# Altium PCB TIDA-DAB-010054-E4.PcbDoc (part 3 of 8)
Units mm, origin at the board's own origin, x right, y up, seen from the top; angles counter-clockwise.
Board outline 300 x 180 mm, 4 copper layers (Top Layer, Inner Layer1, Inner Layer2, Bottom Layer), stack 1.605 mm thick; 873 components, 388 nets, 2405 pads, 1542 vias.
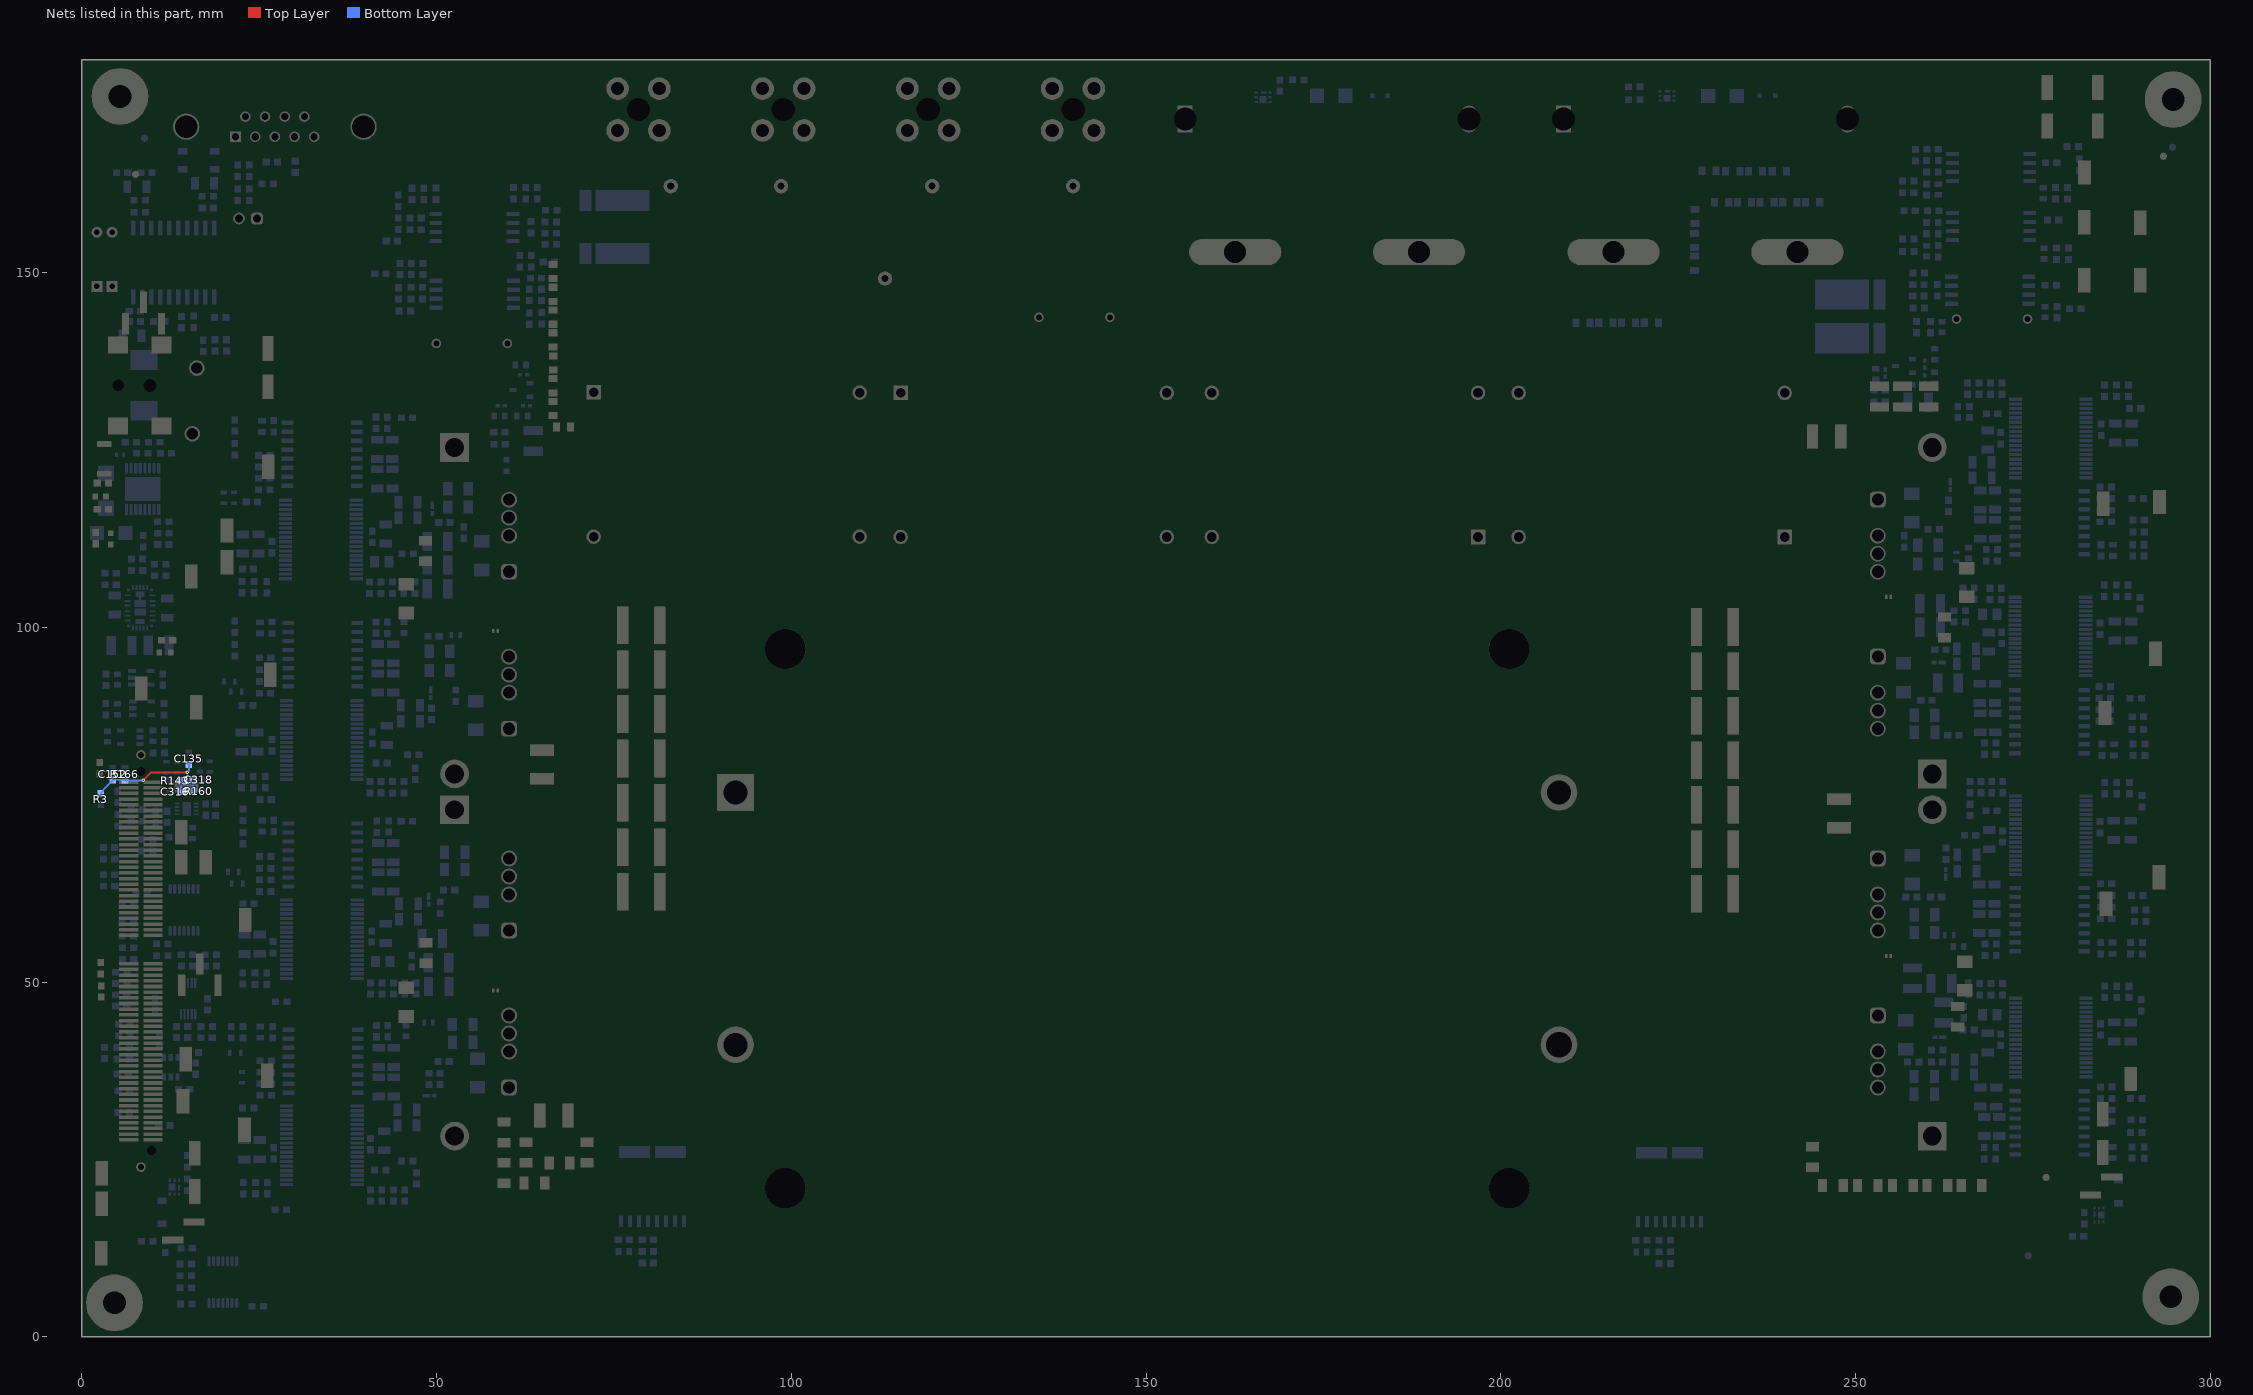
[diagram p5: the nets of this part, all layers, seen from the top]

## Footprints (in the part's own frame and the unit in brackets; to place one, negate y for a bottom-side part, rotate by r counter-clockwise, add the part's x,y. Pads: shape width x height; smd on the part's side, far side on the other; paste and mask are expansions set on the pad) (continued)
LTST-C193_Red [mm] "SMD, 2-Leads, Body1.6x0.8mm"
  rect 0.8x0.8 smd: 1(-0.75,0) 2(0.75,0)
  silkscreen extent -1.2,-0.9 1.85,0.9, body extent -0.85,-0.45 0.85,0.45, height 0.45
Mill-Max_999-11-113-10-000000 [mil] "Shorting Jumper, 7.62mm, 2 Position, Gold, TH"
  rect 60x60 hole 30: 1(-150,0)
  round 60 hole 30: 2(150,0)
  silkscreen extent -102,-12 98,12, body extent -161,-11 161,11, height 105
Net-Tie7milsWide_20milsLong [mil] "7 mils wide by 20 mils long"
  rect 10x7 smd paste-5 mask-5: 1(-5,0) 2(5,0)
"NY PMS 440 0025 PH" [mm] "4-40 nylon screw and mounting hole"
  round 8 hole 3.2: 1(0,0)
  body extent -3.3,-3.3 3.3,3.3, height 2.69
Pb-Free_Overlay_Medium [mm]
  silkscreen extent -2.41,-2.41 2.41,2.41
PW0014A_N [mm] "TSOP, 14-Leads, Body 5x4.4mm, Pitch 0.65mm, IPC Medium Density"
  oval 1.4x0.45 smd: 1(-2.95,1.95) 2(-2.95,1.3) 3(-2.95,0.65) 4(-2.95,0) 5(-2.95,-0.65) 6(-2.95,-1.3) 7(-2.95,-1.95) 8(2.95,-1.95) 9(2.95,-1.3) 10(2.95,-0.65) 11(2.95,0) 12(2.95,0.65) 13(2.95,1.3) 14(2.95,1.95)
  silkscreen extent -3.4,-2.55 1.85,2.55, body extent -3.21,-2.5 3.21,2.5, height 1
PWP0016H-MFG [mm]
  rrect22% 1.5x0.45 smd paste+0 mask+0: 1(-2.9,2.275) 2(-2.9,1.625) 3(-2.9,0.975) 4(-2.9,0.325) 5(-2.9,-0.325) 6(-2.9,-0.975) 7(-2.9,-1.625) 8(-2.9,-2.275) 9(2.9,-2.275) 10(2.9,-1.625) 11(2.9,-0.975) 12(2.9,-0.325) 13(2.9,0.325) 14(2.9,0.975) 15(2.9,1.625) 16(2.9,2.275)
  rrect3% 3.4x5 smd paste-1000 mask-1000: 17(0,0)
  silkscreen extent -4.32,-2.95 2.25,2.95, body extent -3.2,-2.5 3.2,2.5, height 1.2
RDH0030A-MFG [mm]
  round 0.419 smd paste+0 mask+0: 1(-1.633,2.508) 21(1.633,2.508)
  rrect40% 0.85x0.25 smd paste+0 mask+0: 2(-1.775,1.775) 3(-1.775,0.975) 4(-1.775,0.325) 5(-1.775,-0.475) 6(-1.775,-1.125) 7(-1.775,-1.775) 15(1.775,-1.775) 16(1.775,-1.125) 17(1.775,-0.475) 18(1.775,0.325) 19(1.775,0.975) 20(1.775,1.775)
  round 0.407 smd paste+0 mask+0: 8(-1.633,-2.53) 14(1.633,-2.53)
  rrect40% 0.25x0.7 smd paste+0 mask+0: 9(-1,-2.85) 10(-0.5,-2.85) 11(0,-2.85) 12(0.5,-2.85) 13(1,-2.85) 22(1,2.85) 23(0.5,2.85) 24(0,2.85) 25(-0.5,2.85) 26(-1,2.85)
  rrect14% 1.25x0.74 smd paste-1000 mask-1000: 27(0,1.925) 30(0,-1.925)
  rrect10% 1.6x1 smd paste-1000 mask-1000: 28(0,0.6) 29(0,-0.6)
  Top Layer region: 2.2,2.35 2.196,2.331 2.185,2.315 2.169,2.304 2.15,2.3 2.15,2.3 1.875,2.3 1.871,2.281 1.86,2.265 1.844,2.254 1.825,2.25 1.825,2.25 1.425,2.25 1.406,2.254 1.39,2.265 1.379,2.281 1.375,2.3 1.375,2.3 1.375,3.15 1.379,3.169 1.39,3.185 1.406,3.196 1.425,3.2 1.425,3.2 1.575,3.2 1.6,3.193 1.618,3.175 1.625,3.15 1.625,3.15 1.625,2.925 1.629,2.906 1.64,2.89 1.656,2.879 1.675,2.875 1.675,2.875 1.8,2.875 1.825,2.868 1.843,2.85 1.85,2.825 1.85,2.825 1.85,2.6 1.854,2.581 1.865,2.565 1.881,2.554 1.9,2.55 1.9,2.55 2.15,2.55 2.175,2.543 2.193,2.525 2.2,2.5 2.2,2.5
  Top Layer region: 2.2,-2.35 2.196,-2.331 2.185,-2.315 2.169,-2.304 2.15,-2.3 2.15,-2.3 1.875,-2.3 1.871,-2.281 1.86,-2.265 1.844,-2.254 1.825,-2.25 1.825,-2.25 1.425,-2.25 1.406,-2.254 1.39,-2.265 1.379,-2.281 1.375,-2.3 1.375,-2.3 1.375,-3.15 1.379,-3.169 1.39,-3.185 1.406,-3.196 1.425,-3.2 1.425,-3.2 1.575,-3.2 1.6,-3.193 1.618,-3.175 1.625,-3.15 1.625,-3.15 1.625,-2.925 1.629,-2.906 1.64,-2.89 1.656,-2.879 1.675,-2.875 1.675,-2.875 1.8,-2.875 1.825,-2.868 1.843,-2.85 1.85,-2.825 1.85,-2.825 1.85,-2.6 1.854,-2.581 1.865,-2.565 1.881,-2.554 1.9,-2.55 1.9,-2.55 2.15,-2.55 2.175,-2.543 2.193,-2.525 2.2,-2.5 2.2,-2.5
  Top Layer region: -2.2,-2.35 -2.196,-2.331 -2.185,-2.315 -2.169,-2.304 -2.15,-2.3 -2.15,-2.3 -1.875,-2.3 -1.871,-2.281 -1.86,-2.265 -1.844,-2.254 -1.825,-2.25 -1.825,-2.25 -1.425,-2.25 -1.406,-2.254 -1.39,-2.265 -1.379,-2.281 -1.375,-2.3 -1.375,-2.3 -1.375,-3.15 -1.379,-3.169 -1.39,-3.185 -1.406,-3.196 -1.425,-3.2 -1.425,-3.2 -1.575,-3.2 -1.6,-3.193 -1.618,-3.175 -1.625,-3.15 -1.625,-3.15 -1.625,-2.925 -1.629,-2.906 -1.64,-2.89 -1.656,-2.879 -1.675,-2.875 -1.675,-2.875 -1.8,-2.875 -1.825,-2.868 -1.843,-2.85 -1.85,-2.825 -1.85,-2.825 -1.85,-2.6 -1.854,-2.581 -1.865,-2.565 -1.881,-2.554 -1.9,-2.55 -1.9,-2.55 -2.15,-2.55 -2.175,-2.543 -2.193,-2.525 -2.2,-2.5 -2.2,-2.5
  Top Layer region: -2.2,2.35 -2.196,2.331 -2.185,2.315 -2.169,2.304 -2.15,2.3 -2.15,2.3 -1.875,2.3 -1.871,2.281 -1.86,2.265 -1.844,2.254 -1.825,2.25 -1.825,2.25 -1.425,2.25 -1.406,2.254 -1.39,2.265 -1.379,2.281 -1.375,2.3 -1.375,2.3 -1.375,3.15 -1.379,3.169 -1.39,3.185 -1.406,3.196 -1.425,3.2 -1.425,3.2 -1.575,3.2 -1.6,3.193 -1.618,3.175 -1.625,3.15 -1.625,3.15 -1.625,2.925 -1.629,2.906 -1.64,2.89 -1.656,2.879 -1.675,2.875 -1.675,2.875 -1.8,2.875 -1.825,2.868 -1.843,2.85 -1.85,2.825 -1.85,2.825 -1.85,2.6 -1.854,2.581 -1.865,2.565 -1.881,2.554 -1.9,2.55 -1.9,2.55 -2.15,2.55 -2.175,2.543 -2.193,2.525 -2.2,2.5 -2.2,2.5
  silkscreen extent -2.42,-3.65 2.05,3.65, body extent -2,-3 2,3, height 1.9
SMA [mm] "Molded Diode, 2-Leads, Body 4.3x2.6mm, IPC Medium Density, based on OnSemi component dimensions and land pattern"
  rect 2x2 smd: 1(-2,0) 2(2,0)
  silkscreen extent -3.66,-1.57 2.79,1.57, body extent -2.6,-1.3 2.6,1.3, height 2.42
SMC_Bi [mil] "SMC, no polarity mark"
  rect 110x150 smd: 1(-140.49,0) 2(140.49,0)
  body extent -156,-116 156,116, height 92
SOD-123 [mm] "On Semi recommended land pattern"
  rect 0.915x1.22 smd: 1(-1.637,0) 2(1.637,0)
  silkscreen extent -2.74,-1.17 2.03,1.17, body extent -1.93,-0.9 1.93,0.9, height 1.35
SOD-323 [mm] "NXP recommended land pattern"
  rect 0.6x0.6 smd paste-0.05: 1(-1.1,0) 2(1.1,0)
  silkscreen extent -2.06,-0.86 1.53,0.86, body extent -1.3,-0.67 1.3,0.68, height 1.1
SW_SKRKAE [mm] "SMD, 2-Leads, Body 3.9x2.9mm"
  rrect12% 0.8x2 smd: 1(-2.1,0) 2(2.1,0)
  body extent -2.4,-1.45 2.4,1.45, height 2
Testpoint_Keystone_Miniature [mil] "Miniature SMT test point"
  rect 135x70 smd: 1(0,0)
  silkscreen extent -78,-46 78,45, body extent -52,-20 52,20, height 61
TI_Stacked_Overlay_Small [mm]
  silkscreen extent -10.63,-2.49 10.63,2.49
TNPW0603 [mm] "Vishay"
  rect 0.5x0.9 smd: 1(-0.75,0) 2(0.75,0)
  silkscreen extent -0.2,-0.6 0.2,0.6, body extent -0.85,-0.47 0.85,0.47, height 0.55
TO-247-4 [mm] "FM, 4-Leads, Body 15.94x5.02mm, Pitch 2.54mm"
  rrect50% 2.24x2.24 hole 1.7: 1(-5.08,0)
  round 2.24 hole 1.7: 2(0,0) 3(2.54,0) 4(5.08,0)
  silkscreen extent -8.07,-2.49 8.07,2.72, body extent -8.07,-2.49 8.07,2.72, height 27.97
UWT_630x770 [mm] "SMD, 2-Leads, Dia 6.3mm"
  rrect6% 3.5x1.6 smd: 1(-2.7,0) 2(2.7,0)
  body extent -3.5,-3.3 3.5,3.3, height 8
WEEE_Minimum [mm] "WEEElie bin"
  silkscreen extent -2.42,-4.38 2.52,2.65
WL-SMCW_GREEN [mm] "WURTH"
  rect 0.8x0.8 smd: 1(-0.8,0) 2(0.8,0)
  silkscreen extent -1.9,-0.8 1.2,0.8, body extent -0.85,-0.45 0.85,0.45, height 0.8
WSL3637_0_002 [mil] "Vishay WSL3637 recommended land pattern for 0.002 to 0.01 Ohm"
  rect 116x300 smd: 1(-147,-45) 2(147,-45)
  rect 116x66 smd: 3(-147,162) 4(147,162)
  silkscreen extent -220,-210 220,210, body extent -185,-190 185,190, height 35
Wurth_61000218321 [mm] "Header, 2.54mm, 2x1, SMT"
  rect 1x3 smd: 1(-1.27,1.5) 2(1.27,-1.5)
  silkscreen extent -2.86,-1.27 2.54,1.27, body extent -2.54,-2.5 2.54,2.5, height 6.3
Wurth_61000318221 [mm] "Header, 2.54mm, 3x1, SMT"
  rrect10% 3x1 smd: 1(-1.4,2.54) 2(1.6,0) 3(-1.4,-2.54)
  body extent -2.5,-3.81 2.5,3.81, height 9.33
WURTH_61300211121 [mm] "Header, 2.54mm, 2x1, TH"
  rrect50% 1.65x1.65 hole 1.15: 1(-1.27,0)
  round 1.65 hole 1.15: 2(1.27,0)
  body extent -2.54,-1.27 2.54,1.27, height 8.54
Wurth_618009231121 [mm] "Receptacle, D-Sub, 9 Position, R/A, TH"
  rect 1.5x1.5 hole 1: 1(-10.92,5.54)
  round 1.5 hole 1: 2(-10.92,2.77) 3(-10.92,0) 4(-10.92,-2.77) 5(-10.92,-5.54) 6(-8.08,4.155) 7(-8.08,1.385) 8(-8.08,-1.385) 9(-8.08,-4.155)
  round 3.7 hole 3.2: 10(-9.5,12.5) 11(-9.5,-12.5)
  silkscreen extent -12.78,-15.4 -0.53,15.4, body extent -12.5,-15.4 6,15.4, height 12.5
Wurth_WP-THRBU [mm] "Power Element Bush, M3, TH"
  round 3.2 hole 1.85: 1(-2.935,-2.935) 1(-2.935,2.935) 1(2.935,-2.935) 1(2.935,2.935)
  round 3.1 on Top Paste: ""(-2.935,-2.935) ""(-2.935,2.935) ""(2.935,-2.935) ""(2.935,2.935)
  round 3 hole 3.3 unplated mask+0.102: ""(0,0)
  silkscreen extent -3.5,-3.5 3.5,3.5, body extent -3.5,-3.5 3.5,3.5, height 3

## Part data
C1 C4 C6 C12 C313 C319 C320 C321 C322: library part CMP-0006848-4, "CAP, CERM, 0.01 uF, 100 V, +/- 5%, X7R, 0603", Cap_Case=0603, Manufacturer=Kemet, Supplier Part Number 1=399-3190-1-ND, TempCo=X7R, Tolerance_%=5%, Value1=Unknown, Value2=100V, ValueDisplayed=0.01uF
C2 C8 C14: library part CMP-0080740-1, "CAP, CERM, 10 µF, 25 V,+/- 10%, X7R, 1206", Cap_Case=1206, Manufacturer=TDK, Supplier Part Number 1=445-7705-1-ND, TempCo=X7R, Tolerance_%=10%, Value2=25V, ValueDisplayed=10µF
C3 C7 C13: library part CMP-0085302-1, "CAP, CERM, 1 µF, 16 V,+/- 10%, X7R, AEC-Q200 Grade 1, 0603", Cap_Case=0603, Manufacturer="Samsung Electro-Mechanics", TempCo=X7R, Tolerance_%=10%, Value2=16V, ValueDisplayed=1µF
C5 C154 C197: library part CMP-0006837-4, "CAP, CERM, 0.1 uF, 50 V, +/- 10%, X7R, 0603", Cap_Case=0603, Manufacturer="Wurth Elektronik", TempCo=X7R, Tolerance_%=10%, Value1=Unknown, Value2=50V, ValueDisplayed=0.1uF
C9 C11: library part CMP-0007220-4, "CAP, CERM, 47 pF, 50 V, +/- 5%, C0G/NP0, 0603", Cap_Case=0603, Manufacturer=MuRata, Supplier Part Number 1=490-1419-1-ND, TempCo=C0G/NP0, Tolerance_%=5%, Value1=Unknown, Value2=50V, ValueDisplayed=47pF
C10: library part CMP-0006987-4, "CAP, CERM, 4700 pF, 50 V, +/- 10%, X7R, 0603", Cap_Case=0603, Manufacturer=Kemet, Supplier Part Number 1=399-5337-1-ND, TempCo=X7R, Tolerance_%=10%, Value1=Unknown, Value2=50V, ValueDisplayed=4700pF
C15 C16 C19 C20 C25 C26 C28 C30: library part CMP-0009324-2, "CAP, CERM, 0.1 uF, 1000 V, +/- 10%, X7R, 1812", Cap_Case=1812, Manufacturer=Kemet, Supplier Part Number 1=399-6493-1-ND, TempCo=X7R, Tolerance_%=10%, Value1=Unknown, Value2=1000V, ValueDisplayed=0.1uF
C21 C22: library part CMP-0120640-1, "30 µF Film Capacitor 800V Polypropylene (PP), Metallized Radial - 4 Leads", Digikey Part Number=495-B32716H8306K000-ND, Manufacturer=TDK, Mouser Part Number=871-B32716H8306K000, Operating Temperature Range="-55°C to +105°C", Tolerance_%=10%, ValueDisplayed=30uF
C23 C24: library part CMP-0120639-1, "Power Film Capacitor, 15 uF, 1.1 kVDC, ± 10%, Metallized PP, Radial Box - 4 Pin, Through Hole", Digikey Part Number=495-B32716H1156K000-ND, Manufacturer=TDK, Mouser Part Number=871-B32716H1156K000, Operating Temperature Range="-55°C to +105°C", Tolerance_%=10%, ValueDisplayed=15uF
C31 C33 C35 C37 C39 C41 C43 C45 C47 C49 C51 C53 C55 C57: library part CMP-0086177-1, "CAP, CERM, 0.47 µF, 1000 V,+/- 10%, X7R, AEC-Q200 Grade 1, 2220", Cap_Case=2220, Manufacturer="Knowles Capacitors", TempCo=X7R, Tolerance_%=10%, Value2=1000V, ValueDisplayed=0.47µF
C32 C34 C36 C38 C40 C42 C44 C46 C48 C50 C52 C54 C56 C58: library part CMP-0860865-1, "CAP, CERM, 0.47 µF, 630 V,+/- 20%, X7T, AEC-Q200 Grade 1, 2220", Cap_Case=2220, Manufacturer=TDK, TempCo=X7T, Tolerance_%=20%, Value2=630V, ValueDisplayed=0.47µF
C59 C60 C61: library part CMP-0009601-2, "CAP, CERM, 2200 pF, 3KV, +/- 20%, E, Cap, 7x12x9 mm", Cap_Case=CAPRD1000W60D900H1200, Manufacturer=MuRata, Supplier Part Number 1=490-7047-ND, TempCo=E, Tolerance_%=20%, Value1=Unknown, Value2=250V, ValueDisplayed=2200pF
C62 C85 C86 C91 C116 C117 C120: library part CMP-0006356-2, "CAP, CERM, 0.1 uF, 50 V, +/- 10%, X7R, AEC-Q200 Grade 1, 0402", Cap_Case=0402, Manufacturer=MuRata, Supplier Part Number 1=490-10672-1-ND, TempCo=X7R, Tolerance_%=10%, Value1=Unknown, Value2=50V, ValueDisplayed=0.1uF
C63 C65 C67 C69: library part CMP-0007121-4, "CAP, CERM, 2.2 uF, 16 V, +/- 10%, X7R, 0603", Cap_Case=0603, Manufacturer="Taiyo Yuden", Supplier Part Number 1=EMK107BB7225KA-T-ND, TempCo=X7R, Tolerance_%=10%, Value1=Unknown, Value2=16V, ValueDisplayed=2.2uF
C64 C68 C78 C80 C81 C88 C94 C95 C97 C99 C102 C104 C126 C146 C151: library part CMP-0121051-1, "Automotive CAP, 100㎋, 25V, ±10%, X7R, 0603, 5mm Bending", Manufacturer=Samsung, Mouser Part Number=187-CL10B104KA8VPJC, Operating Temperature Range="-55°C to +125°C", TempCo=15%, Temperature Characteristic=X7R, Tolerance_%=10%, ValueDisplayed=100nF
C66 C77: library part CMP-0007038-5, "CAP, CERM, 0.22 uF, 16 V, +/- 10%, X7R, 0603", Cap_Case=0603, Manufacturer=TDK, Supplier Part Number 1=445-1318-1-ND, TempCo=X7R, Tolerance_%=10%, Value1="0.0125 ohm", Value2=16V, ValueDisplayed=0.22uF
C70: library part CMP-0007136-5, "CAP, CERM, 1 uF, 16 V, +/- 10%, X7R, AEC-Q200 Grade 1, 0603", Cap_Case=0603, Manufacturer=MuRata, Supplier Part Number 1=490-5241-6-ND, TempCo=X7R, Tolerance_%=10%, Value1=Unknown, Value2=16V, ValueDisplayed=1uF
C71 C72: library part CMP-0009220-2, "CAP, CERM, 47 uF, 10 V, +/- 10%, X7R, 1210", Cap_Case=1210, Manufacturer=MuRata, Supplier Part Number 1=490-5312-1-ND, TempCo=X7R, Tolerance_%=10%, Value1=Unknown, Value2=10V, ValueDisplayed=47uF
C73 C96 C138 C145 C314: library part CMP-0081462-1, "CAP, AL, 100 µF, 25 V, +/- 20%, SMD", Cap_Case=6.3x7.7mm, Manufacturer=Nichicon, Supplier Part Number 1=493-2190-1-ND, Tolerance_%=20%, Value2=25V, ValueDisplayed=100µF
C74 C75: library part CMP-0008802-2, "CAP, CERM, 10 uF, 50 V, +/- 10%, X7R, 1206", Cap_Case=1206, Manufacturer=Samsung, Supplier Part Number 1=1276-6767-1-ND, TempCo=X7R, Tolerance_%=10%, Value1=Unknown, Value2=50V, ValueDisplayed=10uF
C76: library part CMP-0007208-4, "CAP, CERM, 33 pF, 50 V, +/- 5%, C0G/NP0, 0603", Cap_Case=0603, Manufacturer=MuRata, Supplier Part Number 1=490-1415-1-ND, TempCo=C0G/NP0, Tolerance_%=5%, Value1=Unknown, Value2=50V, ValueDisplayed=33pF
C79 C82 C98 C100 C101 C103 C129 C131 C142 C143: library part CMP-0079605-1, "CAP, CERM, 2.2 µF, 16 V,+/- 10%, X7R, 0603", Cap_Case=0603, Manufacturer="Yageo America", Supplier Part Number 1=311-3490-1-ND, TempCo=X7R, Tolerance_%=10%, Value2=16V, ValueDisplayed=2.2µF
C83 C92 C93 C107 C108 C123 C127 C239 C263 C267 C271 C272 C273: library part CMP-0006811-4, "CAP, CERM, 10 pF, 10 V, +/- 10%, X7R, 0603", Cap_Case=0603, Manufacturer=AVX, Supplier Part Number 1=0603ZC100KAT2A-ND, TempCo=X7R, Tolerance_%=10%, Value1=Unknown, Value2=10V, ValueDisplayed=10pF
C84 C87 C90 C111 C115 C118 C119 C148: library part CMP-0121052-1, "Cap Ceramic 1uF 25V X7R ±10% Pad SMD 0603 +125°C T/R", Digikey Part Number=1276-CL10B105KA8VPJCCT-ND, Manufacturer=Samsung, Mouser Part Number=187-CL10B105KA8VPJC, Operating Temperature Range="-55°C to +125°C", TempCo=15%, Temperature Characteristic=X7R, Tolerance_%=10%, ValueDisplayed=1uF
C89 C124: library part CMP-0006810-4, "CAP, CERM, 0.082 uF, 16 V, +/- 10%, X7R, 0603", Cap_Case=0603, Manufacturer=AVX, Supplier Part Number 1=478-1238-1-ND, TempCo=X7R, Tolerance_%=10%, Value1="0.042 ohm", Value2=16V, ValueDisplayed=0.082uF
C105 C106: library part CMP-0006970-4, "CAP, CERM, 82 pF, 50 V, +/- 10%, C0G/NP0, 0603", Cap_Case=0603, Manufacturer=Kemet, Supplier Part Number 1=399-1059-1-ND, TempCo=C0G/NP0, Tolerance_%=10%, Value1=Unknown, Value2=50V, ValueDisplayed=82pF
C109: library part CMP-0007197-4, "CAP, CERM, 220 pF, 50 V, +/- 5%, C0G/NP0, 0603", Cap_Case=0603, Manufacturer=MuRata, Supplier Part Number 1=490-1435-1-ND, TempCo=C0G/NP0, Tolerance_%=5%, Value1=Unknown, Value2=50V, ValueDisplayed=220pF
C110 C147: library part CMP-0006753-4, "CAP, CERM, 0.1 uF, 25 V, +/- 10%, X7R, 0603", Cap_Case=0603, Manufacturer=AVX, Supplier Part Number 1=478-3714-1-ND, TempCo=X7R, Tolerance_%=10%, Value1="0.05 ohm", Value2=25V, ValueDisplayed=0.1uF
C112 C149 C155 C157 C198 C200 C237 C275 C325 C326 C327 C328 C329 C330 C331 C332: library part CMP-0085950-1, "CAP, CERM, 10 µF, 50 V,+/- 10%, X7R, AEC-Q200 Grade 1, 1206", Cap_Case=1206, Manufacturer=TDK, TempCo=X7R, Tolerance_%=10%, Value2=50V, ValueDisplayed=10µF
C113 C150 C156 C158 C159 C160 C165 C167 C199 C201 C202 C203 C208 C210 C232 C236 C238 C244 C246 C276 C277 C280 C282 C285: library part CMP-0007078-4, "CAP, CERM, 0.1 uF, 50 V, +/- 10%, X7R, AEC-Q200 Grade 1, 0603", Cap_Case=0603, Manufacturer=TDK, Supplier Part Number 1=445-5666-1-ND, TempCo=X7R, Tolerance_%=10%, Value1="0.0296 ohm", Value2=50V, ValueDisplayed=0.1uF
C114 C140 C153 C323 C324 C333 C334: library part CMP-0860987-1, "CAP, CERM, 3900 pF, 100 V,+/- 5%, C0G/NP0, 0603", Cap_Case=0603, Manufacturer=TDK, TempCo=C0G/NP0, Tolerance_%=5%, Value2=100V, ValueDisplayed=3900pF
C121 C122 C136 C137: library part CMP-0006839-4, "CAP, CERM, 10 pF, 50 V, +/- 5%, C0G/NP0, 0603", Cap_Case=0603, Manufacturer=Kemet, Supplier Part Number 1=399-1049-1-ND, TempCo=C0G/NP0, Tolerance_%=5%, Value1=Unknown, Value2=50V, ValueDisplayed=10pF
C125 C193: library part CMP-0007210-4, "CAP, CERM, 3300 pF, 50 V, +/- 5%, C0G/NP0, 0603", Cap_Case=0603, Manufacturer=MuRata, Supplier Part Number 1=GRM1885C1H332JA01D-ND, TempCo=C0G/NP0, Tolerance_%=5%, Value1=Unknown, Value2=50V, ValueDisplayed=3300pF
C128 C139: library part CMP-0007490-4, "CAP, CERM, 1000 pF, 250 V, +/- 10%, X7R, 0603", Cap_Case=0603, Manufacturer=MuRata, Supplier Part Number 1=490-3526-1-ND, TempCo=X7R, Tolerance_%=10%, Value1=Unknown, Value2=250V, ValueDisplayed=1000pF
C130 C132 C141 C144: library part CMP-0007077-5, "CAP, CERM, 0.1 uF, 25 V, +/- 10%, X7R, AEC-Q200 Grade 1, 0603", Cap_Case=0603, Manufacturer=TDK, Supplier Part Number 1=445-5667-1-ND, TempCo=X7R, Tolerance_%=10%, Value1=Unknown, Value2=25V, ValueDisplayed=0.1uF
C133 C134 C194 C195 C315 C316 C317 C318: library part CMP-0006784-4, "CAP, CERM, 330 pF, 50 V, +/- 5%, C0G/NP0, 0603", Cap_Case=0603, Manufacturer=AVX, Supplier Part Number 1=478-1181-1-ND, TempCo=C0G/NP0, Tolerance_%=5%, Value1="0.071 ohm", Value2=50V, ValueDisplayed=330pF
C135: library part CMP-0007468-5, "CAP, CERM, 0.01 uF, 100 V, +/- 10%, X7R, 0603", Cap_Case=0603, Manufacturer=MuRata, Supplier Part Number 1=GRM188R72A103KA01D-ND, TempCo=X7R, Tolerance_%=10%, Value1=Unknown, Value2=100V, ValueDisplayed=0.01uF
C152: library part CMP-0006975-4, "CAP, CERM, 0.01 uF, 25 V, +/- 5%, C0G/NP0, 0603", Cap_Case=0603, Manufacturer=Kemet, Supplier Part Number 1=399-5779-1-ND, TempCo=C0G/NP0, Tolerance_%=5%, Value1=Unknown, Value2=25V, ValueDisplayed=0.01uF
C161 C162 C163 C164 C188 C189 C204 C205 C206 C207 C230 C235 C240 C241 C242 C243 C269 C278 C279 C283 C284 C302 C308 C312: library part CMP-0006921-4, "CAP, CERM, 330 pF, 50 V, +/- 10%, X7R, 0603", Cap_Case=0603, Manufacturer=Kemet, Supplier Part Number 1=399-1073-1-ND, TempCo=X7R, Tolerance_%=10%, Value1=Unknown, Value2=50V, ValueDisplayed=330pF
C166 C168 C209 C211 C245 C247 C281 C286: library part CMP-0008698-2, "CAP, CERM, 2.2 uF, 50 V, +/- 10%, X7R, 1206", Cap_Case=1206_180, Manufacturer=TDK, Supplier Part Number 1=445-7697-1-ND, TempCo=X7R, Tolerance_%=10%, Value1="0.005887 ohm", Value2=50V, ValueDisplayed=2.2uF
C169 C171 C173 C176 C178 C181 C196 C213 C215 C218 C220 C223 C248 C250 C252 C255 C257 C260 C287 C289 C291 C294 C296 C300: library part CMP-0008586-2, "CAP, CERM, 0.1 uF, 50 V, +/- 10%, X7R, 1206", Cap_Case=1206, Manufacturer=Kemet, Supplier Part Number 1=399-1249-1-ND, TempCo=X7R, Tolerance_%=10%, Value1="0.059 ohm", Value2=50V, ValueDisplayed=0.1uF
C170 C172 C212 C214 C249 C251 C288 C290: library part CMP-0008661-2, "CAP, CERM, 3.3 uF, 50 V, +/- 10%, X5R, 1206", Cap_Case=1206_180, Manufacturer=TDK, Supplier Part Number 1=445-5992-1-ND, TempCo=X5R, Tolerance_%=10%, Value1="0.004773 ohm", Value2=50V, ValueDisplayed=3.3uF
C174 C177 C216 C219 C253 C256 C292 C295: library part CMP-0008710-2, "CAP, CERM, 1 uF, 100 V, +/- 10%, X7R, 1206", Cap_Case=1206_180, Manufacturer=TDK, Supplier Part Number 1=445-4467-1-ND, TempCo=X7R, Tolerance_%=10%, Value1="0.004575 ohm", Value2=100V, ValueDisplayed=1uF
C175 C180 C183 C184 C185 C190 C217 C222 C225 C226 C227 C231 C254 C259 C262 C264 C265 C270 C293 C299 C303 C304 C305 C309: library part CMP-0080091-1, "CAP, CERM, 100 pF, 50 V,+/- 1%, C0G/NP0, 0603", Cap_Case=0603, Manufacturer=Kemet, Supplier Part Number 1=399-7819-1-ND, TempCo=C0G/NP0, Tolerance_%=1%, Value2=50V, ValueDisplayed=100pF
C179 C182 C221 C224 C258 C261 C297 C301: library part CMP-0008701-2, "CAP, CERM, 0.47 uF, 50 V, +/- 10%, X7R, 1206", Cap_Case=1206_180, Manufacturer=TDK, Supplier Part Number 1=445-1380-1-ND, TempCo=X7R, Tolerance_%=10%, Value1="0.009426 ohm", Value2=50V, ValueDisplayed=0.47uF
C186 C191 C228 C233 C266 C274 C306 C310: library part CMP-0121053-1, "Automotive CAP, 1㎌, 35V, ±10%, X7R, 0603, 5mm Bending", Manufacturer=Samsung, Mouser Part Number=187-CL10B105KL9VPJC, Operating Temperature Range="-55°C to +125°C", TempCo=15%, Temperature Characteristic=X7R, Tolerance_%=10%, ValueDisplayed=1uF
C187 C192 C229 C234 C268 C298 C307 C311: library part CMP-0006815-4, "CAP, CERM, 0.1 uF, 10 V, +/- 10%, X7R, 0603", Cap_Case=0603, Manufacturer=AVX, Supplier Part Number 1=478-7939-1-ND, TempCo=X7R, Tolerance_%=10%, Value1=Unknown, Value2=10V, ValueDisplayed=0.1uF
D1 D3: library part CMP-0077069-2, "Diode, Standard Recovery Rectifier, 250 V, 0.2 A, SOD-323", Manufacturer="Micro Commercial Components", Value1=0.2A, Value2=1.25V
D2 D4: library part CMP-0005523-4, "Diode, Zener, 12 V, 1.5 W, SMA", Manufacturer="ON Semiconductor", Power_W=1.5W
D5: library part CMP-0086728-1, "Diode TVS Single Bi-Dir 36V 600W 2-Pin SMB", Manufacturer=Littelfuse
D6: library part CMP-0079922-3, "LED, Red, SMD", Color=Red, Manufacturer=Lite-On, Value1=W, Value2=2V
D7: library part CMP-0005697-3, "Diode, TVS, Bi, 36 V, 58.1 Vc, SMC", Manufacturer=Littelfuse, Value1=1500W
D8 D10 D11 D12: library part CMP-0002894-2, "LED, Green, SMD", Color=green, Manufacturer="Wurth Elektronik", Value1=W, Value2=2V
D9: library part CMP-0028405-2, "Diode, Schottky, 50 V, 2 A, SMA", Manufacturer="Diodes Inc.", Value1=2A, Value2=0.7V
D13 D16: library part CMP-0028951-2, "Diode, Schottky, 60 V, 0.5 A, SOD-123", Manufacturer="Diodes Inc.", Value1=0.5A, Value2=0.5V
D14 D15 D18 D19 D22 D24 D25 D26 D27 D28 D29 D30: library part CMP-0095286-1, "Diode Standard 1200 V 1A Surface Mount DO-214AC (SMA)", Digikey Part Number=US1Q-TPMSCT-ND, Forward Current=1A, Manufacturer=MCC, Max Surge Forward Current=30A, Mouser Part Number=833-US1Q-TP, Operating Temperature Range="-55°C to +150°C", Peak Reverse Current=5uA, ValueDisplayed=45pF
D17 D20 D21 D23 D31 D32 D33 D34: library part CMP-0093310-1, "Standard LEDs - SMD Green TOPLED E 1608", Color=Green, Forward Current=2mA, Manufacturer="Osram Opto", Mouser Part Number=720-KGDELLS122A4849, Operating Temperature Range="-40°C to +110°C"
FID1 FID2 FID3 FID4 FID5 FID6: library part CMP-0077181-1, "Fiducial mark.  There is nothing to buy or mount.", Manufacturer=N/A
H1 H2 H3 H4: library part CMP-0003617-1, "Machine Screw, Round, #4-40 x 1/4, Nylon, Philips panhead", Manufacturer="B&F Fastener Supply", Supplier Part Number 1=H542-ND
H5 H6 H7 H8: library part CMP-0003610-1, "Standoff, Hex, 0.5\"L #4-40 Nylon", Manufacturer=Keystone, Supplier Part Number 1=36-1902C-ND
J1 J3: library part CMP-0054787-1, "Header, 2.54mm, 2x1, Gold, SMT", Color=Black, Manufacturer="Wurth Elektronik"
J2: library part CMP-0003814-2, "C2000 controlCARD-120HSEC connector, SMT", Manufacturer=Samtec
J4 J5: library part CMP-0079473-1, "Header, 2.54mm, 3x1, Gold, SMT", Color=Black, Current_A=3A, Manufacturer="Wurth Elektronik", Voltage_V=250V
J6: library part CMP-0054820-2, "Receptacle, D-Sub, 9 Position, R/A, TH", Color=Black, Current_A=3A, Manufacturer="Wurth Elektronik", Supplier Part Number 1=16T0655, Voltage_V=125V
J8 J9: library part CMP-0055045-1, "Shorting Jumper, 7.62mm, 2 Position, Gold, TH", Manufacturer=Mill-Max, Supplier Part Number 1=ED1334-ND
J10: library part CMP-0054794-2, "Header, 2.54 mm, 2x1, Gold, TH", Color=Black, Manufacturer="Wurth Elektronik", Supplier Part Number 1=732-5315-ND
J11 J12 J13 J14: library part CMP-0078526-1, "Power Element Bush, M3, TH", Current_A=50A, Manufacturer="Wurth Elektronik", Supplier Part Number 1=732-10882-1-ND
J15: library part CMP-0075012-1, "Power Jack, SMT", Manufacturer="CUI Inc.", Supplier Part Number 1=CP-002AHPJDKR-ND
K1 K3: library part CMP-0049812-1, "General Purpose Relay SPST-NO (1 Form A) 12VDC Coil Through Hole", Coil Current_A=235.3mA, Coil Power_W=2.8W, Coil Resistance=51Ω, Coil Voltage_VDC=12V, Contact Rating_A=50A, Digikey Part Number=39-G9KB-1ADC12-ND, Manufacturer=Omron, Mouser Part Number=653-G9KB-1ADC12, Operating Temperature Range="-40°C to +85°C"
L1 L2 L4 L5 L6 L7 L8 L9 L10 L11 L12 L13 L14 L15 L17 L18: library part CMP-0003155-2, "Ferrite Bead, 26 ohm @ 100 MHz, 6.5 A, 0603", Manufacturer="Wurth Elektronik", Supplier Part Number 1=732-6117-1-ND, Value1="0.005 ohm", Value2=6.5A, ValueDisplayed="26 ohm"
L3: library part CMP-0084086-1, "100µH @ 100kHz 2 Line Common Mode Choke Surface Mount 5.8 kOhms @ 10MHz 150mA DCR 2Ohm", Digikey Part Number=445-3959-1-ND, Impedance At Frequency="5800Ω @ 10MHz", Manufacturer=TDK, Mouser Part Number=810-ACT45B1012PTL003, Operating Temperature Range="-40°C to +150°C", Test Frequency=100kHz, Tolerance_%=+50/-30%
LBL1: library part CMP-0003625-1, "Thermal Transfer Printable Labels, 0.650\" W x 0.200\" H - 10,000 per roll", Manufacturer=Brady, Supplier Part Number 1=97C5133
LOGO1 LOGO2: library part CMP-0074835-1, "IEC 61010-1 High Voltage Warning"
LOGO3 LOGO4 LOGO5 LOGO6 LOGO7 LOGO8 LOGO9 LOGO10 LOGO11 LOGO12: library part CMP-0074837-1, "IEC 61010-1 Hot Surface Warning"
Logo13: library part CMP-0074844-1
Logo14: library part CMP-0074769-1
Logo15: library part CMP-0074847-1, "FCC_disclaimer"
Logo16: library part CMP-0074839-1
Logo17: library part CMP-0074836-1, "IEC 61010-1 Caution Warning"
Logo18: library part CMP-0074840-1, "ESD Susceptible Symbol"
Logo19: library part CMP-0074838-1, "Texas Instrument Corporate Signature"
MP1 MP2 MP4 MP5 MP8 MP9 MP11 MP12: library part CMP-0098314-1, "CD-02-05 Series 0.95 x 0.75 inch w/ Hole TO-247 Phase Change Thermal Pad", Digikey Part Number=345-1545-ND, Manufacturer=Wakefield-Vette, Mouser Part Number=567-CD-02-05-247, Operating Temperature Range=to
MP3 MP6 MP7 MP10: library part CMP-0091185-1, "Heat Sinks Aluminum heatsink 50mmdegreased", Digikey Part Number=CR201-50VE-ND, Manufacturer=Ohmite, Mating Package=TO-247/TO-264, Mouser Part Number=588-CR201-50VE, Natural Thermal Resistance=3.3°C/W, Operating Temperature Range=to
MP13 MP14 MP15 MP16: library part CMP-0120966-2, "Hex Standoff Threaded #8-32 Brass 0.500\" (12.70mm) 1/2\"", Digikey Part Number=36-1474C-ND, Manufacturer="Keystone Electronics", Mouser Part Number=534-1474C, Operating Temperature Range=to
MP17 MP18 MP19 MP20: library part CMP-0093555-1, "#8-32 Pan Head Machine Screw Phillips Drive Stainless Steel", Digikey Part Number=H717-ND, Manufacturer="Building Fasteners", Operating Temperature Range=to
NT1: library part CMP-0078142-5, "Single point connection between nets.", Manufacturer=N/A
PWM1 PWM2 PWM3 PWM4 PWM5 PWM6 PWM7 PWM8 TP6 TP8 TP9 TP10 TP12 TP13 TP14 TP15 TP16 TP17 TP18 TP19 TP20 TP21 TP22 TP23 TP24 TP25 TP26 TP27 TP28 TP29 TP31: library part CMP-0055152-2, "Test Point, Miniature, SMT", Manufacturer="Keystone Electronics", Supplier Part Number 1=36-5015TR-ND
Q1 Q2 Q3 Q4: library part CMP-0076725-1, "30-V N-Channel NexFET™ Power MOSFET", Manufacturer="Texas Instruments"
Q6 Q7 Q10 Q11: library part CMP-0084898-1, "MOSFET, N-CH, 900 V, 63 A, TO-247-4", Alternate Manufacturer=None, Manufacturer=Cree, Value1="? ohm", Value2="87 nC"
Q8 Q9 Q12 Q13: library part CMP-0085490-1, "MOSFET, N-CH, 1200 V, 30 A, TO-247-4", Alternate Manufacturer=None, Manufacturer=Cree, Value1="? ohm", Value2="51 nC"
R1 R4 R39 R48: library part CMP-0023921-2, "RES, 200, 0.1%, 0.1 W, 0603", Manufacturer="Yageo America", Power_W=100mW, TempCo="25 ppm/C", Tolerance_%=0.1%, Value2=0.1W, Value_Code=200R, ValueDisplayed=200
R2 R5 R43 R51 R158: library part CMP-0023653-3, "RES, 10.0 k, 0.1%, 0.1 W, 0603", Manufacturer="Yageo America", Power_W=100mW, TempCo="25 ppm/C", Tolerance_%=0.1%, Value2=0.1W, Value_Code=10k0, ValueDisplayed=10.0k
R3 R10 R15 R19 R22 R23 R36 R38 R41 R61 R63 R85 R137 R141 R144 R147 R150 R193 R194 R206 R207 R210 R211 R212 R213 R251 R252 R263 R264: library part CMP-0023343-3, "RES, 0, 1%, 0.1 W, AEC-Q200 Grade 0, 0603", Manufacturer="Stackpole Electronics Inc", Power_W=100mW, Supplier Part Number 1=RMCF0603ZT0R00CT-ND, TempCo=ppm/C, Tolerance_%=1%, Value2=0.1W, Value_Code=0
R6 R7 R20 R21: library part CMP-0018745-2, "RES, 1.0, 5%, 0.5 W, 1206", Manufacturer=Bourns, Power_W=500mW, Supplier Part Number 1=652-CRM1206JW1R0ELF, TempCo="150 ppm/C", Tolerance_%=5%, Value2=0.5W, Value_Code=1R00, ValueDisplayed=1.0
R8 R12: library part CMP-0021853-2, "RES, 604, 1%, 0.5 W, 0805", Manufacturer=Panasonic, Power_W=500mW, Supplier Part Number 1=667-ERJ-P06F6040V, TempCo="100 ppm/C", Tolerance_%=1%, Value2=0.5W, Value_Code=604R, ValueDisplayed=604
R9 R11: library part CMP-0021848-2, "RES, 1.00 k, 1%, 0.25 W, 0805", Manufacturer=Panasonic, Power_W=250mW, Supplier Part Number 1=P16058CT-ND, TempCo="100 ppm/C", Tolerance_%=1%, Value2=0.25W, Value_Code=1k00, ValueDisplayed=1.00k
R13 R14: library part CMP-0025756-4, "RES, 220, 5%, 0.1 W, AEC-Q200 Grade 0, 0603", Manufacturer=Vishay-Dale, Power_W=100mW, Supplier Part Number 1=541-220GCT-ND, TempCo="200 ppm/C", Tolerance_%=5%, Value2=0.1W, Value_Code=220R, ValueDisplayed=220
R16 R17 R18 R29: library part CMP-0091849-1, "Res Thin Film 0603 10Ohm 5% 1/8W ±100ppm/°C Molded T/R", Digikey Part Number=716-CH0603-10RJFTATR-ND, Manufacturer=Vishay, Mouser Part Number=71-CH0603-10RJFTA, Operating Temperature Range="-55°C to +155°C", Power_W=125mW, TempCo=100ppm/°C, Tolerance_%=5%
R24 R25 R26 R27 R28 R31 R32 R34 R35 R52 R79 R82 R174 R175 R176 R177 R178 R179 R180 R181 R182 R186 R190 R204 R205 R232 R233 R234 R235 R236 R237 R238 R239 R240 R244 R248 R287 R292 R330 R345: library part CMP-0021998-4, "RES, 10.0 k, 1%, 0.1 W, AEC-Q200 Grade 0, 0603", Manufacturer=Vishay-Dale, Power_W=100mW, Supplier Part Number 1=541-10.0KHCT-ND, TempCo="100 ppm/C", Tolerance_%=1%, Value2=0.1W, Value_Code=10k0, ValueDisplayed=10.0k
R30 R33 R42 R86: library part CMP-0023143-5, "RES, 49.9, 1%, 0.1 W, 0603", Manufacturer=Yageo, Power_W=100mW, Supplier Part Number 1=311-49.9HRCT-ND, TempCo="100 ppm/C", Tolerance_%=1%, Value2=0.1W, Value_Code=49R9, ValueDisplayed=49.9
R37 R45: library part CMP-0025942-5, "RES, 8.2 k, 5%, 0.1 W, 0603", Manufacturer=Yageo, Power_W=100mW, Supplier Part Number 1=311-8.2KGRCT-ND, TempCo="100 ppm/C", Tolerance_%=5%, Value2=0.1W, Value_Code=8k20, ValueDisplayed=8.2k
R40: library part CMP-0025906-5, "RES, 2.2 k, 5%, 0.1 W, 0603", Manufacturer=Yageo, Power_W=100mW, Supplier Part Number 1=311-2.2KGRCT-ND, TempCo="100 ppm/C", Tolerance_%=5%, Value2=0.1W, Value_Code=2k20, ValueDisplayed=2.2k
R46: library part CMP-0025894-5, "RES, 1.2 k, 5%, 0.1 W, 0603", Manufacturer=Yageo, Power_W=100mW, Supplier Part Number 1=311-1.2KGRCT-ND, TempCo="100 ppm/C", Tolerance_%=5%, Value2=0.1W, Value_Code=1k20, ValueDisplayed=1.2k
R53 R56: library part CMP-0094956-1, "0 Ohms Jumper 0.1W, 1/10W Chip Resistor 0603 (1608 Metric) - Thick Film", Digikey Part Number=2679-CR0603-10W-000TTR-ND, Manufacturer=Venkel, Operating Temperature Range="-55°C to +155°C", Power_W=100mW
R54 R55: library part CMP-0022500-4, "RES, 56.2, 1%, 0.1 W, AEC-Q200 Grade 0, 0603", Manufacturer=Vishay-Dale, Power_W=100mW, Supplier Part Number 1=541-56.2HCT-ND, TempCo="100 ppm/C", Tolerance_%=1%, Value2=0.1W, Value_Code=56R2, ValueDisplayed=56.2
R58: library part CMP-0082607-1, "RES, 0.003, 1%, 3 W, AEC-Q200 Grade 0, 9.14x9.4mm", Manufacturer=Vishay-Dale, Power_W=3W, Supplier Part Number 1=WSLI-.003CT-ND, TempCo="50 ppm/C", Tolerance_%=1%, Value_Code=3L000, ValueDisplayed=0.003
R59: library part CMP-0091524-1, "1.5 mOhms ±1% 3W Chip Resistor Nonstandard Anti-Sulfur, Automotive AEC-Q200, Current Sense, Moisture Resistant, Pulse Withstanding Metal Element", Digikey Part Number=541-10345-1-ND, Manufacturer=Vishay, Mouser Part Number=71-WSL36371L500FEA, Operating Temperature Range="-65°C to +170°C", Power_W=3W, TempCo=75ppm/°C, Tolerance_%=1%
R64 R95 R96 R97 R98 R100 R101 R102 R103 R105 R106 R107 R108 R109 R110 R111 R112 R124 R145 R146 R148 R149 R151 R152: library part CMP-0020237-2, "RES, 634 k, 0.1%, 0.125 W, 0805", Manufacturer="Yageo America", Power_W=125mW, TempCo="25 ppm/C", Tolerance_%=0.1%, Value2=0.125W, Value_Code=634k
R66 R127 R128 R222 R226 R228 R281 R285 R327 R359 R361 R363: library part CMP-0016716-3, "RES, 1.00 M, 1%, 0.25 W, AEC-Q200 Grade 0, 1206", Manufacturer=Vishay-Dale, Power_W=250mW, Supplier Part Number 1=541-1.00MFCT-ND, TempCo="100 ppm/C", Tolerance_%=1%, Value2=0.25W, Value_Code=1M00, ValueDisplayed=1.00M
R68 R77 R78: library part CMP-0025885-5, "RES, 0, 5%, 0.1 W, 0603", Manufacturer=Yageo, Power_W=100mW, Supplier Part Number 1=311-0.0GRCT-ND, TempCo="200 ppm/C", Tolerance_%=5%, Value2=0.1W, Value_Code=0000, ValueDisplayed=0
R69: library part CMP-0023032-4, "RES, 330 k, 1%, 0.1 W, 0603", Manufacturer=Yageo, Power_W=100mW, Supplier Part Number 1=311-330KHRCT-ND, TempCo="100 ppm/C", Tolerance_%=1%, Value2=0.1W, Value_Code=330k
R70 R76: library part CMP-0022983-5, "RES, 2.10 k, 1%, 0.1 W, 0603", Manufacturer=Yageo, Power_W=100mW, Supplier Part Number 1=311-2.10KHRCT-ND, TempCo="100 ppm/C", Tolerance_%=1%, Value2=0.1W, Value_Code=2k10, ValueDisplayed=2.10k
R71: library part CMP-0025900-5, "RES, 20 k, 5%, 0.1 W, 0603", Manufacturer=Yageo, Power_W=100mW, Supplier Part Number 1=311-20KGRCT-ND, TempCo="100 ppm/C", Tolerance_%=5%, Value2=0.1W, Value_Code=20k0, ValueDisplayed=20k
R72 R185 R187 R243 R245 R286 R291 R329 R344: library part CMP-0025698-4, "RES, 100 k, 5%, 0.1 W, AEC-Q200 Grade 0, 0603", Manufacturer=Vishay-Dale, Power_W=100mW, Supplier Part Number 1=541-100KGCT-ND, TempCo="200 ppm/C", Tolerance_%=5%, Value2=0.1W, Value_Code=100k
R73: library part CMP-0022511-4, "RES, 5.36 k, 1%, 0.1 W, AEC-Q200 Grade 0, 0603", Manufacturer=Vishay-Dale, Power_W=100mW, Supplier Part Number 1=541-5.36KHCT-ND, TempCo="100 ppm/C", Tolerance_%=1%, Value2=0.1W, Value_Code=5k36, ValueDisplayed=5.36k
R74: library part CMP-0022860-5, "RES, 19.1 k, 1%, 0.1 W, 0603", Manufacturer=Yageo, Power_W=100mW, Supplier Part Number 1=311-19.1KHRCT-ND, TempCo="100 ppm/C", Tolerance_%=1%, Value2=0.1W, Value_Code=19k1, ValueDisplayed=19.1k
R75: library part CMP-0023020-5, "RES, 30.0 k, 1%, 0.1 W, 0603", Manufacturer=Yageo, Power_W=100mW, Supplier Part Number 1=311-30.0KHRCT-ND, TempCo="100 ppm/C", Tolerance_%=1%, Value2=0.1W, Value_Code=30k0, ValueDisplayed=30.0k
R80: library part CMP-0860025-1, "RES, 40.0 k, 0.1%, 0.15 W, AEC-Q200 Grade 0, 0603", Manufacturer="Vishay Thin Film", Power_W=150mW, TempCo="25 ppm/C", Tolerance_%=0.1%, Value2=0.15W, Value_Code=40k0, ValueDisplayed=40.0k
R81: library part CMP-0082532-1, "RES, 499, 1%, 0.1 W, 0603", Manufacturer=Vishay-Dale, Power_W=100mW, Supplier Part Number 1=541-3986-1-ND, TempCo="100 ppm/C", Tolerance_%=1%, Value2=0.1W, Value_Code=499R, ValueDisplayed=499
R83 R163 R169: library part CMP-0023404-3, "RES, 10.0 k, 0.1%, 0.1 W, 0603", Manufacturer="Susumu Co Ltd", Power_W=100mW, Supplier Part Number 1=RG16P10.0KBCT-ND, TempCo="25 ppm/C", Tolerance_%=0.1%, Value2=0.1W, Value_Code=10k0, ValueDisplayed=10.0k
R84: library part CMP-0022792-5, "RES, 13.0 k, 1%, 0.1 W, 0603", Manufacturer=Yageo, Power_W=100mW, Supplier Part Number 1=311-13.0KHRCT-ND, TempCo="100 ppm/C", Tolerance_%=1%, Value2=0.1W, Value_Code=13k0, ValueDisplayed=13.0k
R87 R131: library part CMP-0082530-1, "RES, 100 k, 5%, 0.1 W, 0603", Manufacturer=Vishay-Dale, Power_W=100mW, Supplier Part Number 1=541-3992-1-ND, TempCo="200 ppm/C", Tolerance_%=5%, Value2=0.1W, Value_Code=100k
R88 R129: library part CMP-0083464-1, "RES, 160, 5%, 0.5 W, 1210", Manufacturer=Yageo, Power_W=500mW, TempCo="100 ppm/C", Tolerance_%=5%, Value2=0.5W, Value_Code=160R, ValueDisplayed=160
R89 R91 R136 R140: library part CMP-0025687-2, "RES, 10.0, 0.1%, 0.1 W, 0603", Manufacturer=Vishay-Dale, Power_W=100mW, Supplier Part Number 1=TNP10.0AACT-ND, TempCo="25 ppm/C", Tolerance_%=0.1%, Value2=0.1W, Value_Code=10R0, ValueDisplayed=10.0
R90 R93 R94 R99 R104 R130 R133 R134: library part CMP-0025919-5, "RES, 3.6 k, 5%, 0.1 W, 0603", Manufacturer=Yageo, Power_W=100mW, Supplier Part Number 1=311-3.6KGRCT-ND, TempCo="100 ppm/C", Tolerance_%=5%, Value2=0.1W, Value_Code=3k60, ValueDisplayed=3.6k
R92 R116 R117: library part CMP-0023099-5, "RES, 40.2, 1%, 0.1 W, 0603", Manufacturer=Yageo, Power_W=100mW, Supplier Part Number 1=311-40.2HRCT-ND, TempCo="100 ppm/C", Tolerance_%=1%, Value2=0.1W, Value_Code=40R2, ValueDisplayed=40.2
R114: library part CMP-0024194-2, "RES, 3.32 k, 0.1%, 0.1 W, 0603", Manufacturer="Yageo America", Power_W=100mW, TempCo="25 ppm/C", Tolerance_%=0.1%, Value2=0.1W, Value_Code=3k32, ValueDisplayed=3.32k
R115: library part CMP-0024483-2, "RES, 7.68 k, 0.1%, 0.1 W, 0603", Manufacturer="Yageo America", Power_W=100mW, TempCo="25 ppm/C", Tolerance_%=0.1%, Value2=0.1W, Value_Code=7k68, ValueDisplayed=7.68k
R118: library part CMP-0022736-4, "RES, 100, 1%, 0.1 W, 0603", Manufacturer=Yageo, Power_W=100mW, Supplier Part Number 1=311-100HRCT-ND, TempCo="100 ppm/C", Tolerance_%=1%, Value2=0.1W, Value_Code=100R, ValueDisplayed=100
R123 R164: library part CMP-0023337-3, "RES, 10.0 k, 1%, 0.1 W, 0603", Manufacturer="Vishay Draloric", PartNumber=RCG060310K0FKEA, Power_W=100mW, Supplier Part Number 1=541-1784-1-ND, TempCo="100 ppm/C", Tolerance_%=1%, Value2=0.1W, Value_Code=10k0, ValueDisplayed=10.0k
R125 R167: library part CMP-0025825-4, "RES, 51, 5%, 0.1 W, AEC-Q200 Grade 0, 0603", Manufacturer=Vishay-Dale, Power_W=100mW, Supplier Part Number 1=541-51GCT-ND, TempCo="200 ppm/C", Tolerance_%=5%, Value2=0.1W, Value_Code=51R0, ValueDisplayed=51
R126: library part CMP-0023241-5, "RES, 68.0, 1%, 0.1 W, 0603", Manufacturer=Yageo, Power_W=100mW, Supplier Part Number 1=311-68.0HRCT-ND, TempCo="100 ppm/C", Tolerance_%=1%, Value2=0.1W, Value_Code=68R0, ValueDisplayed=68.0
R135 R143 R153 R160: library part CMP-0023603-3, "RES, 8.06 k, 0.1%, 0.1 W, 0603", Manufacturer="Susumu Co Ltd", PartNumber=RG1608P-8061-B-T5, Power_W=100mW, Supplier Part Number 1=RG16P8.06KBCT-ND, TempCo="25 ppm/C", Tolerance_%=0.1%, Value2=0.1W, Value_Code=8k06, ValueDisplayed=8.06k
R138 R142 R156 R159: library part CMP-0025686-1, "RES, 10.0 k, 0.1%, 0.1 W, AEC-Q200 Grade 1, 0603", Manufacturer=Vishay-Dale, Power_W=100mW, Supplier Part Number 1=TNP10.0KAACT-ND, TempCo="25 ppm/C", Tolerance_%=0.1%, Value2=0.1W, Value_Code=10k0, ValueDisplayed=10.0k
R139 R157 R166 R168: library part CMP-0022553-4, "RES, 68.1, 1%, 0.1 W, AEC-Q200 Grade 0, 0603", Manufacturer=Vishay-Dale, Power_W=100mW, Supplier Part Number 1=541-68.1HCT-ND, TempCo="100 ppm/C", Tolerance_%=1%, Value2=0.1W, Value_Code=68R1, ValueDisplayed=68.1
R154 R208 R267 R273 R311 R317 R362 R369: library part CMP-0022816-5, "RES, 15.0 k, 1%, 0.1 W, 0603", Manufacturer=Yageo, Power_W=100mW, Supplier Part Number 1=311-15.0KHRCT-ND, TempCo="100 ppm/C", Tolerance_%=1%, Value2=0.1W, Value_Code=15k0, ValueDisplayed=15.0k
R155 R217 R276 R278 R320 R322 R372 R374: library part CMP-0078662-1, "RES, 18.0 k, 1%, 0.1 W, AEC-Q200 Grade 0, 0603", Manufacturer=Panasonic, Power_W=100mW, Supplier Part Number 1=P18.0KHCT-ND, TempCo="100 ppm/C", Tolerance_%=1%, Value2=0.1W, Value_Code=18k0, ValueDisplayed=18.0k
R171 R223 R282 R284 R325 R326 R377 R378: library part CMP-0023000-5, "RES, 2.00 k, 1%, 0.1 W, 0603", Manufacturer=Yageo, Power_W=100mW, Supplier Part Number 1=311-2.00KHRCT-ND, TempCo="100 ppm/C", Tolerance_%=1%, Value2=0.1W, Value_Code=2k00, ValueDisplayed=2.00k
R172 R173 R230 R231: library part CMP-0025874-4, "RES, 0, 5%, 0.1 W, AEC-Q200 Grade 0, 0603", Manufacturer=Panasonic, Power_W=100mW, Supplier Part Number 1=P0.0GCT-ND, TempCo="600 ppm/C", Tolerance_%=5%, Value2=0.1W, Value_Code=0000, ValueDisplayed=0
R183 R241 R288 R328: library part CMP-0025946-3, "RES, 1.0 k, 5%, 0.1 W, AEC-Q200 Grade 0, 0603", Manufacturer=Vishay-Dale, Power_W=100mW, Supplier Part Number 1=541-2213-1-ND, TempCo="200 ppm/C", Tolerance_%=5%, Value2=0.1W, Value_Code=1k00, ValueDisplayed=1.0k
R188 R191 R246 R249 R289 R293 R331 R346: library part CMP-0023642-3, "RES, 107 k, 0.1%, 0.1 W, 0603", Manufacturer="Yageo America", Power_W=100mW, TempCo="25 ppm/C", Tolerance_%=0.1%, Value2=0.1W, Value_Code=107k
R189 R192 R247 R250 R290 R294 R332 R347: library part CMP-0023508-3, "RES, 30.0 k, 0.1%, 0.1 W, 0603", Manufacturer="Susumu Co Ltd", Power_W=100mW, Supplier Part Number 1=RG16P30.0KBCT-ND, TempCo="25 ppm/C", Tolerance_%=0.1%, Value2=0.1W, Value_Code=30k0, ValueDisplayed=30.0k
R196 R198 R255 R257 R298 R301 R335 R350: library part CMP-0023798-3, "RES, 16.2 k, 0.1%, 0.1 W, 0603", Manufacturer="Yageo America", Power_W=100mW, TempCo="25 ppm/C", Tolerance_%=0.1%, Value2=0.1W, Value_Code=16k2, ValueDisplayed=16.2k
R197 R199 R256 R258 R299 R302 R336 R351: library part CMP-0024283-3, "RES, 49.9 k, 0.1%, 0.1 W, 0603", Manufacturer="Yageo America", Power_W=100mW, TempCo="25 ppm/C", Tolerance_%=0.1%, Value2=0.1W, Value_Code=49k9, ValueDisplayed=49.9k
R200 R201 R202 R203 R214 R220 R259 R260 R261 R262 R279 R280 R303 R304 R305 R306 R323 R324 R352 R353 R354 R355 R375 R376: library part CMP-0025700-4, "RES, 100, 5%, 0.1 W, AEC-Q200 Grade 0, 0603", Manufacturer=Vishay-Dale, Power_W=100mW, Supplier Part Number 1=541-100GCT-ND, TempCo="200 ppm/C", Tolerance_%=5%, Value2=0.1W, Value_Code=100R, ValueDisplayed=100
R209 R215 R216 R218 R272 R274 R275 R277 R316 R318 R319 R321 R368 R370 R371 R373: library part CMP-0018648-3, "RES, 2.0, 5%, 0.25 W, AEC-Q200 Grade 0, 1206", Manufacturer=Vishay-Dale, Power_W=250mW, Supplier Part Number 1=541-2.0ECT-ND, TempCo="200 ppm/C", Tolerance_%=5%, Value2=0.25W, Value_Code=2R00, ValueDisplayed=2.0
R219 R221 R224 R225 R227 R229 R338 R339 R340 R341 R342 R343 R379 R380 R381: library part CMP-0015016-3, "RES, 0, 1%, 0.5 W, AEC-Q200 Grade 0, 1210", Manufacturer=Vishay-Dale, Power_W=500mW, Supplier Part Number 1=541-0.0VCT-ND, TempCo=ppm/C, Tolerance_%=1%, Value2=0.5W, Value_Code=0
RT1 RT2 RT3 RT4: library part CMP-0084566-1, "Thermistor, DEC0002A (X1SON-2)", Alternate Manufacturer="Texas Instruments", Alternate PartNumber=TMP6131DECT
S1: library part CMP-0085606-1, "Switch, SPST-NO, 0.05 A, 12 VDC, SMT", CurrentRating_mA=50A, Manufacturer=Alps
T1: library part CMP-0091486-2, "10kW SMPS Transformer, 24:15, 100kHz, 5000VDC Dielectric, 130x90x52mm", Frequency_Fixed=100-200kHz, Manufacturer="Payton Planar", Operating Temperature Range=to, Voltage_Isolation_Vrms=5000VDC
TP1 TP2 TP3 TP4 TP5: library part CMP-0055140-1, "Test Point, Miniature, Orange, TH", Color=Orange, Manufacturer=Keystone, Supplier Part Number 1=36-5003-ND
TP7: library part CMP-0055147-2, "Test Point, Multipurpose, Red, TH", Color=Red, Manufacturer="Keystone Electronics", Supplier Part Number 1=36-5010-ND
TP11: library part CMP-0055148-2, "Test Point, Multipurpose, Black, TH", Color=Black, Manufacturer="Keystone Electronics", Supplier Part Number 1=36-5011-ND
U1: library part CMP-0051219-1, "Single 3-Input Positive-AND Gate, DBV0006A, LARGE T&R", F @ Nom Voltage(Max)(Mhz)=150, Generic Part Number=SN74LVC1G11, ICC @ Nom Voltage(Max)(mA)=0.01, Manufacturer="Texas Instruments", Operating Temperature Range(C)="-40 to 125,-40 to 85", Rating=Catalog, tpd @ Nom Voltage(Max)(ns)=20,7.8,6.2,4.6, Voltage(Nom)(V)=1.8,2.5,3.3,5
U2 U15: library part CMP-0097984-1, Manufacturer="Texas Instruments", Operating Temperature Range=to
U3: library part CMP-0092023-2, "Reinforced 5-kVRMS Isolated CAN Transceiver with Integrated lowemissions DC-DC Converter", Manufacturer="Texas Instruments", Max Supply Voltage=5.5V, Min Supply Voltage=1.71V, Nominal Supply Current=0.3-124mA, Operating Temperature Range="-40°C to +105°C"
U4: library part CMP-0089748-2, "42-V, 2-A Industrial eFuse With Integrated Reverse Input Polarity Protection", Manufacturer="Texas Instruments", Max Supply Voltage=42V, Operating Temperature Range="-40°C to +125°C"
U5 U6: library part CMP-0092532-1, "300-mA, Ultra-Low-Noise, Low-IQ, High PSRR LDO", Digikey Part Number=296-TPS7A2033PDBVRCT-ND, Dropout Voltage=145mV, Manufacturer="Texas Instruments", Max Supply Voltage=6V, Min Supply Voltage=1.6V, Mouser Part Number=595-TPS7A2033PDBVR, Nominal Supply Current=6.5uA, Operating Temperature Range="-40°C to +125°C", Output Voltage=3.3V
U7: library part CMP-0097291-1, "High-Density, 3-V to 36-V Input, 1-V to 6-V Output, 2-A Power Module With Enhanced HotRod™ QFN Package", Digikey Part Number=296-TLVM13620RDHRCT-ND, Manufacturer="Texas Instruments", Max Supply Voltage=36V, Min Supply Voltage=3V, Mouser Part Number=595-TLVM13620RDHR, Nominal Supply Current=4uA, Operating Temperature Range="-40°C to +125°C", Output Voltage=1-6V, Switching Frequency=200-2200kHz
U8: library part CMP-0088302-2, ", 4:1, General Purpose Analog Multiplexer", Digikey Part Number=296-TMUX1204DGSRCT-ND, Manufacturer="Texas Instruments", Max Supply Voltage=5.5V, Min Supply Voltage=1.08V, Mouser Part Number=595-TMUX1204DGSR, Nominal Supply Current=0.01uA, On State Resistance=5Ω, Operating Temperature Range="-40°C to +125°C"
U9 U16: library part CMP-0074892-1, "100-mA, 30-V, Fixed-Output, Linear-Voltage Regulator, DBZ0003A (SOT-23-3)", Alternate Manufacturer="Texas Instruments", Alternate PartNumber=TLV76050DBZT
U10: library part CMP-0013494-3, "Small Reinforced Isolated Modulator With +/-50mV Input and CMOS Interface, DWV0008A (SOIC-8)", Alternate Manufacturer="Texas Instruments", Alternate PartNumber=AMC1306M05DWV, Operating Temperature Range="-40 to 125 C", Rating=Catalog
U11: library part CMP-0040683-2, "Precision, 20 MHz, 0.9 pA Ib, RRIO, CMOS Operational Amplifier, 1.8 to 5.5 V, -40 to 125 degC, 8-pin SON (DRG8), Green (RoHS & no Sb/Br)", Manufacturer="Texas Instruments", Total Supply Voltage(Max)(+5V is 5, +/-5V is 10)=5.5, Total Supply Voltage(Min)(+5V is 5, +/-5V is 10)=1.8
U12 U13: library part CMP-0860008-1, "AMC1336 Small, High-Precision, Reinforced Isolated Delta-Sigma Modulator With Input Optimized for Voltage Sensing Applications, DWV0008A (SOIC-8)", Alternate Manufacturer="Texas Instruments", Alternate PartNumber=AMC1336DWV
U14 U24 U27 U28 U32 U33 U36 U39: library part CMP-0034067-2, "Automotive 1.5-W, 12-V VIN, 25-V VOUT, High-Density, > 5 kVRMS, Isolated DC/DC Module", Manufacturer="Texas Instruments", Max Supply Voltage=18V, Min Supply Voltage=8V, Nominal Supply Current=200-270mA, Operating Temperature Range="-40°C to +150°C", Output Voltage=18-25V, Switching Frequency=16MHz
U18: library part CMP-0080587-1, "Precision Reinforced Isolated Amplifier for Current Sensing, DWV0008A (SOIC-8)", Alternate Manufacturer="Texas Instruments"
U21: library part CMP-0078341-1, "Precision, 2-V Input, Reinforced Isolated Amplifier, DWV0008A (SOIC-8)", Alternate Manufacturer="Texas Instruments", Alternate PartNumber=AMC1311BDWV
U25: library part CMP-0040888-1, "Precision, 20 MHz, 0.9 pA Ib, RRIO, CMOS Operational Amplifier, 1.8 to 5.5 V, -40 to 125 degC, 5-pin SOT23 (DBV5), Green (RoHS & no Sb/Br)", Manufacturer="Texas Instruments", Total Supply Voltage(Max)(+5V is 5, +/-5V is 10)=5.5, Total Supply Voltage(Min)(+5V is 5, +/-5V is 10)=1.8
U26 U31: library part CMP-0066280-1, "Quadruple Bus Buffer Gate with 3-State Outputs, PW0014A (TSSOP-14)", Alternate Manufacturer="Texas Instruments", Alternate PartNumber=SN74LVC126APW
U29 U30 U34 U35 U37 U38 U40 U41: library part CMP-0080534-2, "Single Channel Isolated Gate Driver for SiC/IGBT with Advanced Protection and High-CMTI, DW0016B (SOIC-16)", Alternate Manufacturer="Texas Instruments", Alternate PartNumber=UCC21710QDWRQ1
ZZ1: library part CMP-0003616-3
ZZ2: library part CMP-0077236-1
ZZ3: library part CMP-0077237-1
ZZ4: library part CMP-0077238-1

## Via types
v1: diameter 0.5, hole 0.2, Top Layer to Bottom Layer, tented both sides, 1530 vias
v2: diameter 0.5, hole 0.2, Top Layer to Bottom Layer, 12 vias

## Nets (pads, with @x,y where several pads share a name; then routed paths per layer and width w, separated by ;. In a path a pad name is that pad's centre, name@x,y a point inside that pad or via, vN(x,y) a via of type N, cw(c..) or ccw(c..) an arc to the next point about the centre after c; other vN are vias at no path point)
1.65V_1S: C135.1 C152.1 C316.2 C318.2 R3.1 R143.1 R160.1 R166.2 | length 22.1
  Top Layer w0.254: v1(8.719,78.415) 9.852,79.548 v1(14.896,79.548)
  Bottom Layer w0.254: R3.1@2.714,76.596 3.062,76.944 3.062,77.122 4.394,78.454 4.394,78.504 R166.2@6.107,78.504 ; R166.2@6.107,78.479 6.171,78.415 v1(8.719,78.415) ; R143.1@14.027,78.395 14.03,78.392 14.03,77.191 14.33,76.89 14.94,76.89 ; C135.1@15.093,80.664 15.14,80.617 15.14,79.811 14.896,79.567 v1(14.896,79.548) 14.908,79.536 14.908,78.047 14.94,78.015 14.94,76.89 ; C318.2@15.716,78.479 15.716,76.916 R160.1@15.69,76.89 14.94,76.89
